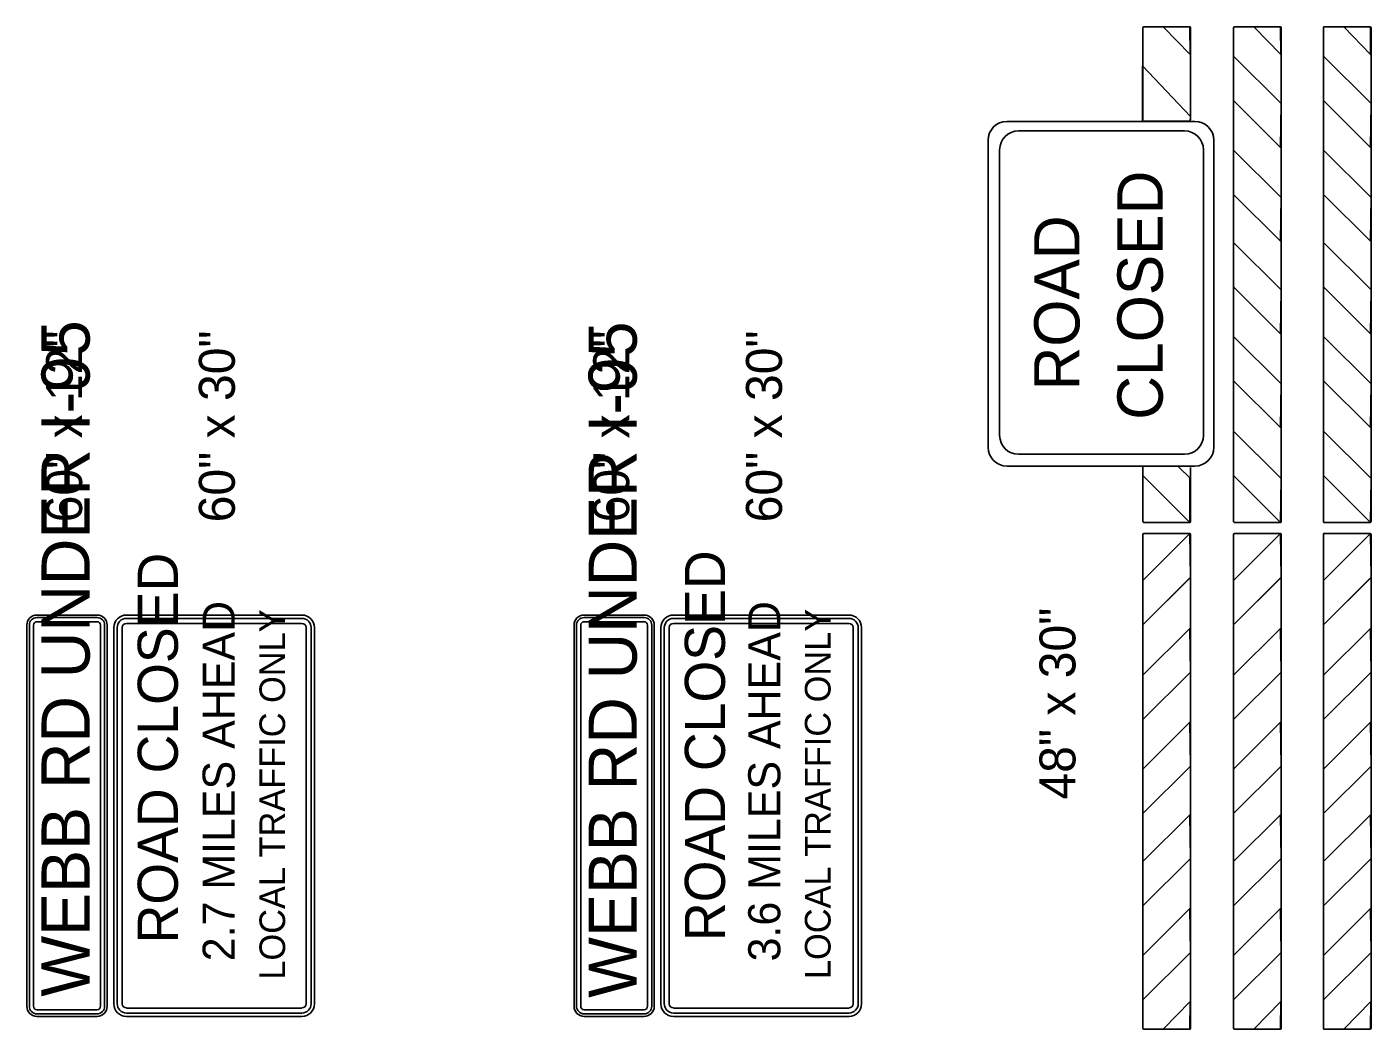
# Model space of a CAD drawing. Extents: x 1123038 to 1172987, y 554419 to 623636.
# Drawn here: x 1156986 to 1161592, y 602541 to 605975 of the extents above; entities that cross this region are included whole.
import ezdxf

# ---------------------------------------------------------------- set-up
doc = ezdxf.new("R2010")
doc.units = 0
for name, color, linetype in [('D_Text_Standard', 7, 'Continuous'), ('Default', 7, 'Continuous'), ('SIGNS TRAFFIC', 7, 'Continuous')]:
    doc.layers.add(name, color=color, linetype=linetype)

msp = doc.modelspace()

# ---------------------------------------------------------------- linework, layer by layer
at = {"layer": 'Default'}
for p, q in [((1160810.1, 605656.2), (1160810.1, 605972.8)), ((1160812.2, 605974.9), (1160971.3, 605974.9)), ((1160973.4, 605659.6), (1160973.4, 605972.8)), ((1161120.7, 604279.6), (1161120.7, 605972.8)), ((1161122.9, 605974.9), (1161281.9, 605974.9)), ((1161284, 604279.6), (1161284, 605972.8)), ((1161428.7, 604279.6), (1161428.7, 605972.8)), ((1161430.9, 605974.9), (1161589.9, 605974.9)), ((1161592, 604279.6), (1161592, 605972.8)), ((1160344.5, 605650.9), (1160988.5, 605650.9)), ((1160384, 605618.6), (1160952.9, 605618.6)), ((1160279.8, 604534.7), (1160279.8, 605586.3)), ((1161053.2, 604534.7), (1161053.2, 605586.3)), ((1160319.3, 604575.3), (1160319.3, 605554)), ((1161017.5, 604575.3), (1161017.5, 605554)), ((1161281.9, 604429.4), (1161120.6, 604589.7)), ((1161589.9, 604429.4), (1161428.6, 604589.7)), ((1160384, 604510.6), (1160952.9, 604510.6)), ((1160344.5, 604470), (1160810, 604470)), ((1160810.1, 604470), (1160988.5, 604470)), ((1160810.1, 604279.6), (1160810.1, 604461.4)), ((1160971.3, 604429.4), (1160934.6, 604465.9)), ((1160973.4, 604279.6), (1160973.4, 604464.8)), ((1160971.3, 604277.4), (1160810, 604437.8)), ((1161281.9, 604277.4), (1161120.6, 604437.8)), ((1161589.9, 604277.4), (1161428.6, 604437.8)), ((1160812.2, 604277.4), (1160971.3, 604277.4)), ((1161122.9, 604277.4), (1161281.9, 604277.4)), ((1161430.9, 604277.4), (1161589.9, 604277.4)), ((1160971.4, 604238.8), (1160810.1, 604078.4)), ((1160810.2, 604236.6), (1160810.2, 602543.4)), ((1160812.3, 604238.8), (1160971.4, 604238.8)), ((1160973.5, 604236.6), (1160973.5, 602543.4)), ((1161282, 604238.8), (1161120.7, 604078.4)), ((1161120.8, 604236.6), (1161120.8, 602543.4)), ((1161123, 604238.8), (1161282, 604238.8)), ((1161284.1, 604236.6), (1161284.1, 602543.4)), ((1161590, 604238.8), (1161428.8, 604078.4)), ((1161428.8, 604236.6), (1161428.8, 602543.4)), ((1161431, 604238.8), (1161590, 604238.8)), ((1161592.1, 604236.6), (1161592.1, 602543.4)), ((1160971.4, 604086.8), (1160810.1, 603926.4)), ((1161282, 604086.8), (1161120.7, 603926.4)), ((1161590, 604086.8), (1161428.8, 603926.4)), ((1160812.3, 602541.2), (1160971.4, 602541.2)), ((1161123, 602541.2), (1161282, 602541.2)), ((1161431, 602541.2), (1161590, 602541.2))]:
    msp.add_line(p, q, dxfattribs=at)
for points in [[(1160972, 605880.7), (1160881.1, 605974.5), (1160971.3, 605974.9)], [(1161282.6, 605880.7), (1161191.7, 605974.5), (1161281.9, 605974.9)], [(1161590.6, 605880.7), (1161499.7, 605974.5), (1161589.9, 605974.9)], [(1160973.2, 605668.2), (1160809.1, 605841), (1160809.1, 605651.5), (1160972.2, 605651.5)], [(1161281.9, 605562), (1161284, 605712), (1161120.6, 605874.3), (1161120.6, 605722.3)], [(1161589.9, 605562), (1161592, 605712), (1161428.6, 605874.3), (1161428.6, 605722.3)], [(1161281.9, 605240.3), (1161284, 605390.3), (1161120.6, 605552.6), (1161120.6, 605400.7)], [(1161589.9, 605240.3), (1161592, 605390.3), (1161428.6, 605552.6), (1161428.6, 605400.7)], [(1161281.9, 604923.6), (1161284, 605073.6), (1161120.6, 605235.9), (1161120.6, 605083.9)], [(1161589.9, 604923.6), (1161592, 605073.6), (1161428.6, 605235.9), (1161428.6, 605083.9)], [(1161281.9, 604601.9), (1161284, 604751.9), (1161120.6, 604914.2), (1161120.6, 604762.2)], [(1161589.9, 604601.9), (1161592, 604751.9), (1161428.6, 604914.2), (1161428.6, 604762.2)], [(1161281.9, 604277.4), (1161284, 604427.4), (1161120.6, 604589.7), (1161120.6, 604437.8)], [(1161589.9, 604277.4), (1161592, 604427.4), (1161428.6, 604589.7), (1161428.6, 604437.8)], [(1160971.4, 604238.8), (1160973.5, 604088.7), (1160810.1, 603926.4), (1160810.1, 604078.4)], [(1161282, 604238.8), (1161284.1, 604088.7), (1161120.7, 603926.4), (1161120.7, 604078.4)], [(1161590, 604238.8), (1161592.1, 604088.7), (1161428.8, 603926.4), (1161428.8, 604078.4)], [(1160971.4, 603914.3), (1160973.5, 603764.3), (1160810.1, 603602), (1160810.1, 603753.9)], [(1161282, 603914.3), (1161284.1, 603764.3), (1161120.7, 603602), (1161120.7, 603753.9)], [(1161590, 603914.3), (1161592.1, 603764.3), (1161428.8, 603602), (1161428.8, 603753.9)], [(1160971.4, 603592.6), (1160973.5, 603442.6), (1160810.1, 603280.3), (1160810.1, 603432.2)], [(1161282, 603592.6), (1161284.1, 603442.6), (1161120.7, 603280.3), (1161120.7, 603432.2)], [(1161590, 603592.6), (1161592.1, 603442.6), (1161428.8, 603280.3), (1161428.8, 603432.2)], [(1160971.4, 603275.8), (1160973.5, 603125.8), (1160810.1, 602963.5), (1160810.1, 603115.5)], [(1161282, 603275.8), (1161284.1, 603125.8), (1161120.7, 602963.5), (1161120.7, 603115.5)], [(1161590, 603275.8), (1161592.1, 603125.8), (1161428.8, 602963.5), (1161428.8, 603115.5)], [(1160971.4, 602954.2), (1160973.5, 602804.1), (1160810.1, 602641.9), (1160810.1, 602793.8)], [(1161282, 602954.2), (1161284.1, 602804.1), (1161120.7, 602641.9), (1161120.7, 602793.8)], [(1161590, 602954.2), (1161592.1, 602804.1), (1161428.8, 602641.9), (1161428.8, 602793.8)], [(1160972.1, 602635.4), (1160881.2, 602541.7), (1160971.4, 602541.2)], [(1161282.7, 602635.4), (1161191.8, 602541.7), (1161282, 602541.2)], [(1161590.7, 602635.4), (1161499.8, 602541.7), (1161590, 602541.2)]]:
    msp.add_lwpolyline(points, close=True, dxfattribs=at)
for points in [[(1160972, 605880.7), (1160971.3, 605974.9), (1160881.1, 605974.5), (1160972, 605880.7)], [(1161282.6, 605880.7), (1161281.9, 605974.9), (1161191.7, 605974.5), (1161282.6, 605880.7)], [(1161590.6, 605880.7), (1161589.9, 605974.9), (1161499.7, 605974.5), (1161590.6, 605880.7)], [(1160972.7, 605659.7), (1160973.2, 605668.2), (1160809.1, 605841), (1160809.1, 605651.5), (1160972.2, 605651.5), (1160972.7, 605659.7)], [(1160810.1, 604470), (1160810, 604437.8), (1160971.3, 604277.4), (1160973.5, 604428), (1160930.4, 604469.4), (1160810, 604470)], [(1160934.3, 604465.6), (1160930.4, 604469.4), (1160810, 604470), (1160810, 604461.4), (1160810.1, 604461.4), (1160810.1, 604437.8), (1160810.1, 604437.7), (1160971.3, 604277.4), (1160971.3, 604279.6), (1160971.3, 604429.4), (1160934.3, 604465.6)], [(1160972.1, 602635.4), (1160971.4, 602541.2), (1160881.2, 602541.7), (1160972.1, 602635.4)], [(1161282.7, 602635.4), (1161282, 602541.2), (1161191.8, 602541.7), (1161282.7, 602635.4)], [(1161590.7, 602635.4), (1161590, 602541.2), (1161499.8, 602541.7), (1161590.7, 602635.4)]]:
    msp.add_lwpolyline(points, dxfattribs=at)
for centre, radius, start, end in [((1160812.2, 605972.8), 2.16, 90, 180), ((1160971.3, 605972.8), 2.16, 360, 90), ((1161122.9, 605972.8), 2.16, 90, 180), ((1161281.9, 605972.8), 2.16, 360, 90), ((1161430.9, 605972.8), 2.16, 90, 180), ((1161589.9, 605972.8), 2.16, 360, 90), ((1160344.5, 605586.3), 64.7, 90, 180), ((1160384, 605554), 64.7, 90, 180), ((1160952.9, 605554), 64.7, 360, 90), ((1160988.5, 605586.3), 64.7, 360, 90), ((1160384, 604575.3), 64.7, 180, 270), ((1160952.9, 604575.3), 64.7, 270, 360), ((1160344.5, 604534.7), 64.7, 180, 270), ((1160988.5, 604534.7), 64.7, 270, 360), ((1160812.2, 604279.6), 2.16, 180, 270), ((1160971.3, 604279.6), 2.16, 270, 360), ((1161122.9, 604279.6), 2.16, 180, 270), ((1161281.9, 604279.6), 2.16, 270, 360), ((1161430.9, 604279.6), 2.16, 180, 270), ((1161589.9, 604279.6), 2.16, 270, 360), ((1160812.3, 604236.6), 2.16, 90, 180), ((1160971.4, 604236.6), 2.16, 360, 90), ((1161123, 604236.6), 2.16, 90, 180), ((1161282, 604236.6), 2.16, 360, 90), ((1161431, 604236.6), 2.16, 90, 180), ((1161590, 604236.6), 2.16, 360, 90), ((1160812.3, 602543.4), 2.16, 180, 270), ((1160971.4, 602543.4), 2.16, 270, 360), ((1161123, 602543.4), 2.16, 180, 270), ((1161282, 602543.4), 2.16, 270, 360), ((1161431, 602543.4), 2.16, 180, 270), ((1161590, 602543.4), 2.16, 270, 360)]:
    msp.add_arc(centre, radius, start, end, dxfattribs=at)
at = {"layer": 'SIGNS TRAFFIC'}
for p, q in [((1157020.4, 603959.9), (1157226.7, 603959.9)), ((1157020.4, 603951.3), (1157226.7, 603951.3)), ((1157327, 603959.9), (1157928.5, 603959.9)), ((1158895.2, 603959.9), (1159101.4, 603959.9)), ((1158895.2, 603951.3), (1159101.4, 603951.3)), ((1159201.7, 603959.9), (1159803.2, 603959.9)), ((1156986.1, 602619.3), (1156986.1, 603925.5)), ((1156994.7, 602619.3), (1156994.7, 603925.5)), ((1157009, 602619.3), (1157009, 603925.5)), ((1157020.4, 603937), (1157226.7, 603937)), ((1157238.2, 603925.5), (1157238.2, 602619.3)), ((1157252.5, 603925.5), (1157252.5, 602619.3)), ((1157261.1, 603925.5), (1157261.1, 602619.3)), ((1157284, 602627.9), (1157284, 603916.9)), ((1157295.4, 602627.9), (1157295.4, 603916.9)), ((1157312.6, 602627.9), (1157312.6, 603916.9)), ((1157327, 603948.4), (1157928.5, 603948.4)), ((1157327, 603931.3), (1157928.5, 603931.3)), ((1157942.8, 603916.9), (1157942.8, 602627.9)), ((1157960, 603916.9), (1157960, 602627.9)), ((1157971.5, 603916.9), (1157971.5, 602627.9)), ((1158860.8, 602619.3), (1158860.8, 603925.5)), ((1158869.4, 602619.3), (1158869.4, 603925.5)), ((1158883.7, 602619.3), (1158883.7, 603925.5)), ((1158895.2, 603937), (1159101.4, 603937)), ((1159112.9, 603925.5), (1159112.9, 602619.3)), ((1159127.2, 603925.5), (1159127.2, 602619.3)), ((1159135.8, 603925.5), (1159135.8, 602619.3)), ((1159158.7, 602627.9), (1159158.7, 603916.9)), ((1159170.2, 602627.9), (1159170.2, 603916.9)), ((1159187.4, 602627.9), (1159187.4, 603916.9)), ((1159201.7, 603948.4), (1159803.2, 603948.4)), ((1159201.7, 603931.3), (1159803.2, 603931.3)), ((1159817.6, 603916.9), (1159817.6, 602627.9)), ((1159834.8, 603916.9), (1159834.8, 602627.9)), ((1159846.2, 603916.9), (1159846.2, 602627.9)), ((1157928.5, 602613.5), (1157327, 602613.5)), ((1159803.2, 602613.5), (1159201.7, 602613.5)), ((1157226.7, 602607.8), (1157020.4, 602607.8)), ((1157226.7, 602593.5), (1157020.4, 602593.5)), ((1157226.7, 602584.9), (1157020.4, 602584.9)), ((1157928.5, 602596.4), (1157327, 602596.4)), ((1157928.5, 602584.9), (1157327, 602584.9)), ((1159101.4, 602607.8), (1158895.2, 602607.8)), ((1159101.4, 602593.5), (1158895.2, 602593.5)), ((1159101.4, 602584.9), (1158895.2, 602584.9)), ((1159803.2, 602596.4), (1159201.7, 602596.4)), ((1159803.2, 602584.9), (1159201.7, 602584.9))]:
    msp.add_line(p, q, dxfattribs=at)
for centre, radius, start, end in [((1157020.4, 603925.5), 34.4, 90, 180), ((1157020.4, 603925.5), 25.8, 90, 180), ((1157226.7, 603925.5), 34.4, 0, 90), ((1157226.7, 603925.5), 25.8, 0, 90), ((1157327, 603916.9), 43, 90, 180), ((1157928.5, 603916.9), 43, 0, 90), ((1158895.2, 603925.5), 34.4, 90, 180), ((1158895.2, 603925.5), 25.8, 90, 180), ((1159101.4, 603925.5), 34.4, 0, 90), ((1159101.4, 603925.5), 25.8, 0, 90), ((1159201.7, 603916.9), 43, 90, 180), ((1159803.2, 603916.9), 43, 0, 90), ((1157020.4, 603925.5), 11.5, 90, 180), ((1157226.7, 603925.5), 11.5, 0, 90), ((1157327, 603916.9), 31.5, 90, 180), ((1157327, 603916.9), 14.3, 90, 180), ((1157928.5, 603916.9), 31.5, 0, 90), ((1157928.5, 603916.9), 14.3, 0, 90), ((1158895.2, 603925.5), 11.5, 90, 180), ((1159101.4, 603925.5), 11.5, 0, 90), ((1159201.7, 603916.9), 31.5, 90, 180), ((1159201.7, 603916.9), 14.3, 90, 180), ((1159803.2, 603916.9), 31.5, 0, 90), ((1159803.2, 603916.9), 14.3, 0, 90), ((1157020.4, 602619.3), 34.4, 180, 270), ((1157020.4, 602619.3), 25.8, 180, 270), ((1157020.4, 602619.3), 11.5, 180, 270), ((1157226.7, 602619.3), 34.4, 270, 0), ((1157226.7, 602619.3), 25.8, 270, 0), ((1157226.7, 602619.3), 11.5, 270, 0), ((1157327, 602627.9), 43, 180, 270), ((1157327, 602627.9), 31.5, 180, 270), ((1157327, 602627.9), 14.3, 180, 270), ((1157928.5, 602627.9), 43, 270, 0), ((1157928.5, 602627.9), 31.5, 270, 0), ((1157928.5, 602627.9), 14.3, 270, 0), ((1158895.2, 602619.3), 34.4, 180, 270), ((1158895.2, 602619.3), 25.8, 180, 270), ((1158895.2, 602619.3), 11.5, 180, 270), ((1159101.4, 602619.3), 34.4, 270, 0), ((1159101.4, 602619.3), 25.8, 270, 0), ((1159101.4, 602619.3), 11.5, 270, 0), ((1159201.7, 602627.9), 43, 180, 270), ((1159201.7, 602627.9), 31.5, 180, 270), ((1159201.7, 602627.9), 14.3, 180, 270), ((1159803.2, 602627.9), 43, 270, 0), ((1159803.2, 602627.9), 31.5, 270, 0), ((1159803.2, 602627.9), 14.3, 270, 0)]:
    msp.add_arc(centre, radius, start, end, dxfattribs=at)

# ---------------------------------------------------------------- texts
at = {"layer": 'D_Text_Standard'}
for s, p in [('60" x 12"', (1157175.3, 604277.5)), ('60" x 30"', (1157698.6, 604277.5)), ('60" x 12"', (1159050, 604277.5)), ('60" x 30"', (1159573.3, 604277.5)), ('48" x 30"', (1160579, 603327.7))]:
    msp.add_text(s, height=123.19, rotation=90, dxfattribs=at).set_placement(p)
at = {"layer": 'Default'}
for s, p in [('CLOSED', (1160878, 604629)), ('ROAD', (1160592.9, 604729.4))]:
    msp.add_text(s, height=155.18, rotation=90, dxfattribs=at).set_placement(p)
at = {"layer": 'SIGNS TRAFFIC'}
for s, height, p in [('WEBB RD UNDER I-95', 165, (1157201.1, 602652.5)), ('WEBB RD UNDER I-95', 165, (1159075.8, 602648.4)), ('ROAD CLOSED', 137.5, (1157503.4, 602834.8)), ('ROAD CLOSED', 137.5, (1159378.1, 602842.9)), ('2.7 MILES AHEAD', 110, (1157698.3, 602773.6)), ('3.6 MILES AHEAD', 110, (1159567.8, 602773.2)), ('LOCAL TRAFFIC ONLY', 88, (1157871, 602710.7)), ('LOCAL TRAFFIC ONLY', 88, (1159739.9, 602712.7))]:
    msp.add_text(s, height=height, rotation=90, dxfattribs=at).set_placement(p)

doc.saveas('drawing.dxf')
